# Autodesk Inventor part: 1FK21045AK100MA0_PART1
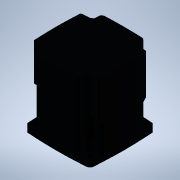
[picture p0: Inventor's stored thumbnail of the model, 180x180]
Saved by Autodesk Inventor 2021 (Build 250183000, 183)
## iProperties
Created: 2025-04
Part Number: 1FK21045AK100MA0_PART1
Material: Generic
Catalog Web Link: www.3dfindit.com
Description: -Servo synchronous motor
Document SubType Name: Modeling
Designer: psAdmin
Mass: 473.602 g
Surface Area: 436.509 cm^2
Volume: 473.602 cm^3
Density: 1 g/cm^3
Appearance: PSOLRGB-176-176-176
Category: PARTsolutions
Title: 1FK21045AK100MA0_PART1
Author: Cadenas PARTsolutions
Comments: Servo synchronous motor
Sending System: PARTsolutions
Preprocessor: ST-DEVELOPER v19.3
PSOL_IDENT_0: {$CADENAS_DATA/23d-libs/siemens_ag/_cat_/e0/5f/1fk21045ak100ma0.prj},213 {VTYP=3D},{NB=1FK21045AK100
PSOL_IDENT_1: MA0_PART1},{LINA=1FK21045AK100MA0_PART1},{NN=1FK21045AK100MA0_PART1},{NOPRJ=TRUE},{DATE=19.08.2025 1
PSOL_IDENT_2: 4:01:03},{GEOMDATE=30.07.2025 02:01:57},{VERSION=},{LINEID=10},{WBVAR=},{WBNUMERIC=}  {NB=1FK21045AK
PSOL_IDENT_3: 100MA0_PART1},{LINA=1FK21045AK100MA0_PART1},{KT=DUMMY},{PREVIEW=../../../_pool_/0f/2c/p_d211_xx_0043
PSOL_IDENT_4: 8j.png},{DESCSHORT=SIMOTICS S-1FK2 HD, SINAMICS S210 3AC 400V-480V, 1.7 Nm, 6000 rpm},{DESCLONG=SIMO
PSOL_IDENT_5: TICS S-1FK2 HD servo motor M0=2.4 Nm; PN = 1.07 kW at nN=6000 rpm (380-480 V); PN = 0.75 kW at nN=30
PSOL_IDENT_6: 00 rpm (200-240 V); with holding brake; degree of protection IP64; cylindrical shaft D19x40mm; absol
PSOL_IDENT_7: ute encoder 22-bit + 12-bit multiturn (encoder AM22DQC); with OCC interface; plug size M17, rotatabl
PSOL_IDENT_8: e; SIMOTICS S-1FK2 servomotorfor a wide range of uses in industrial environments. SIMOTICS S‑1FK2 se
PSOL_IDENT_9: rvomotors are compact synchronous motors with a high dynamic performance that set themselves apart a
PSOL_IDENT_10: s a result of their high power density, degree of protection and overload capability. The motors are
PSOL_IDENT_11: available in two variants: as High Dynamic variant (highest dynamic performance as a result of the
PSOL_IDENT_12: low intrinsic moment of inertia for applications demanding a high dynamic performance with low moved
PSOL_IDENT_13: masses) - and as Compact variant (precise and stable closed-loop control for medium up to large mov
PSOL_IDENT_14: ed masses as a result of a medium intrinsic moment of inertia). SIMOTICSS‑1FK2 servomotors fully exp
PSOL_IDENT_15: loit their strengths in a system with the SINAMICSS210 frequency converter and simple connection usi
PSOL_IDENT_16: ng the one cable connection (OCC). Advantages include the short control and positioning times, fast
PSOL_IDENT_17: and precise correction of disturbing quantities as well as stable control with a high dynamic perfor
PSOL_IDENT_18: mance. The servo motors can be configured to address a wide range of requirements. For example with
PSOL_IDENT_19: and without holding brake, IP64 or IP65 degree of protection, singleturn or multiturn absolute encod
PSOL_IDENT_20: ers - to name just a few. Further, the servomotors are available in different shaft heights extendin
PSOL_IDENT_21: g from 20 to 100. A shaft sealing ring is available to achieve an IP65 degree of protection and for
PSOL_IDENT_22: subsequent mounting at the motor or as spare part. SIMOTICS - the optimum motor for each and every m
PSOL_IDENT_23: otion control application.},{INTNO=804766807114},{SUPPLIERALTNO=1FK2104-5AK10-0MA0},{MANUID=1FK21045
PSOL_IDENT_24: AK100MA0},{MANUNAME=Siemens},{MANUTYPEDESC=Synchronous motor 1FK2-HD 2,39 Nm},{AAU732=SIMOTICS},{AAO
PSOL_IDENT_25: 057=S-1FK2},{AAU734=SIMOTICS S-1FK2 HD servo motor M0=2.4 Nm; PN = 1.07 kW at nN=6000 rpm (380-480 V
PSOL_IDENT_26: ); PN = 0.75 kW at nN=3000 rpm (200-240 V); with holding brake; degree of protection IP64; cylindric
PSOL_IDENT_27: al shaft D19x40mm; absolute encoder 22-bit + 12-bit multiturn (encoder AM22DQC); with OCC interface;
PSOL_IDENT_28: plug size M17, rotatable;},{AAW338=Synchronous motor 1FK2-HD 2,39 Nm},{AAO742=SIMOTICS},{AAO663=404
PSOL_IDENT_29: 2948691236},{NOCUPEROU=1},{PRICEQUANTITY=1},{QUANTITYMIN=1},{QUANTITYINT=1},{CTN=85015100},{COO=DE},
PSOL_IDENT_30: {AAO676=1FK2104-5AK10-0MA0},{AAO677=Siemens AG},{ORDERUNIT=C62},{CONTENTUNIT=C62}
NB: 1FK21045AK100MA0_PART1
NT: Servo synchronous motor
NBSYN: $MANUID._PART1
LINA: 1FK21045AK100MA0_PART1
CATALOG: SIEMENS
PREVIEW: ../../../_pool_/0f/2c/p_d211_xx_00438j.png
DESCSHORT: SIMOTICS S-1FK2 HD, SINAMICS S210 3AC 400V-480V, 1.7 Nm, 6000 rpm
DESCLONG: SIMOTICS S-1FK2 HD servo motor M0=2.4 Nm; PN = 1.07 kW at nN=6000 rpm (380-480 V); PN = 0.75 kW at nN=3000 rpm (200-240 V); with holding brake; degree of protec
INTNO: 804766807114
SUPPLIERALTNO: 1FK2104-5AK10-0MA0
MANUID: 1FK21045AK100MA0
MANUNAME: Siemens
MANUTYPEDESC: Synchronous motor 1FK2-HD 2,39 Nm
AAU732: SIMOTICS
AAO057: S-1FK2
AAU734: SIMOTICS S-1FK2 HD servo motor M0=2.4 Nm; PN = 1.07 kW at nN=6000 rpm (380-480 V); PN = 0.75 kW at nN=3000 rpm (200-240 V); with holding brake; degree of protec
AAW338: Synchronous motor 1FK2-HD 2,39 Nm
AAO742: SIMOTICS
AAO663: 4042948691236.0
NOCUPEROU: 1
PRICEQUANTITY: 1
QUANTITYMIN: 1
QUANTITYINT: 1
CTN: 85015100
COO: DE
ARTICLENO: 1FK21045AK100MA0_PART1
BOMINFO: 1FK21045AK100MA0_PART1
CREATOR: CADENAS GmbH
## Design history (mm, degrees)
feature "2025_04_17_15_45_14_0980"
node "ECLASS_CAX_IMPORTER_001_CP_0_XY"
node "ECLASS_CAX_IMPORTER_001_CP_0_YZ"
node "ECLASS_CAX_IMPORTER_001_CP_0_ZX"
node "ECLASS_CAX_IMPORTER_001_CP_0_X"
node "ECLASS_CAX_IMPORTER_001_CP_0_Y"
node "ECLASS_CAX_IMPORTER_001_CP_0_Z"
node "ECLASS_CAX_IMPORTER_001_CP_0_Center"
node "ECLASS_CAX_IMPORTER_001_CP_1_XY"
node "ECLASS_CAX_IMPORTER_001_CP_1_YZ"
node "ECLASS_CAX_IMPORTER_001_CP_1_ZX"
node "ECLASS_CAX_IMPORTER_001_CP_1_X"
node "ECLASS_CAX_IMPORTER_001_CP_1_Y"
node "ECLASS_CAX_IMPORTER_001_CP_1_Z"
node "ECLASS_CAX_IMPORTER_001_CP_1_Center"
body "Solid1"
